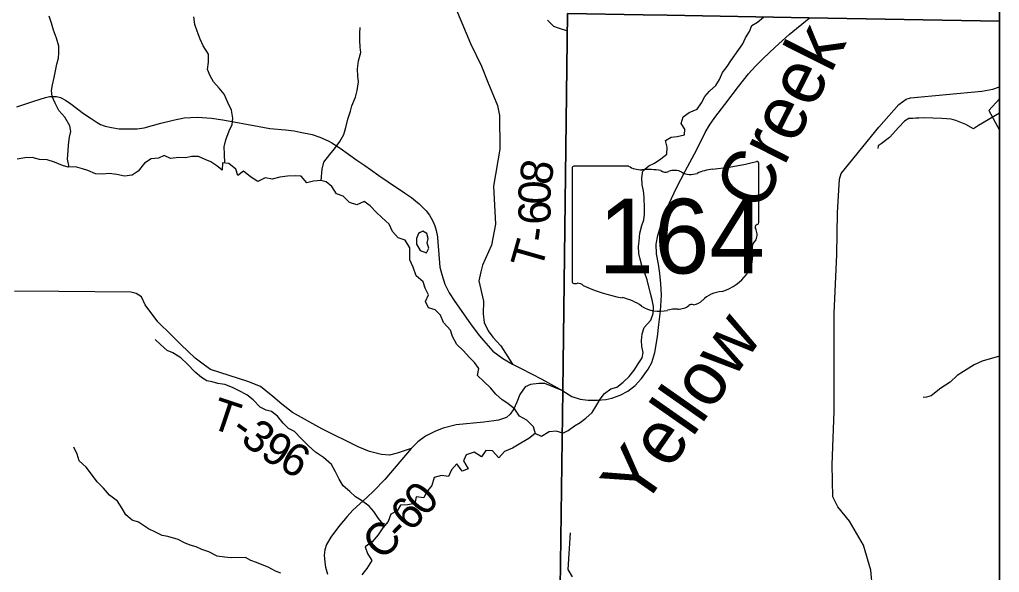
# Model space of a CAD drawing. Extents: x -3.6 to 34, y 0 to 32.8.
# Drawn here: x 1.441 to 3.17, y 27.961 to 28.937 of the extents above; entities that cross this region are included whole.
import ezdxf

# ---------------------------------------------------------------- set-up
doc = ezdxf.new("R2010")
doc.units = 0
for name, color, linetype in [('GM_X_Corporation', 7, 'Continuous'), ('GM_X_County_Road', 7, 'Continuous'), ('GM_X_County_Road_Text', 7, 'Continuous'), ('GM_X_Minor_Lake', 7, 'Continuous'), ('GM_X_Minor_River', 7, 'Continuous'), ('GM_X_Minor_River_Text', 7, 'Continuous'), ('GM_X_State_Location', 7, 'Continuous'), ('GM_X_State_Route', 7, 'Continuous'), ('GM_X_State_Shield', 7, 'Continuous'), ('GM_X_Township_Road', 7, 'Continuous'), ('GM_X_Township_Road_Text', 7, 'Continuous'), ('SH_Data', 7, 'Continuous')]:
    doc.layers.add(name, color=color, linetype=linetype)

msp = doc.modelspace()

# ---------------------------------------------------------------- linework, layer by layer
at = {"layer": 'GM_X_Corporation'}
for points in [[(3.1705, 28.9337), (3.1705, 32.8429), (-3.6295, 32.8429), (-3.6295, 26.0429), (2.3706, 26.0429), (2.3712, 26.0804), (2.3716, 26.1248), (2.3732, 26.2253), (2.3789, 26.6097), (2.3911, 27.5117), (2.3952, 27.9336), (2.3997, 28.282), (2.4082, 28.9473), (2.5416, 28.945), (2.5837, 28.9442), (2.8343, 28.9397)], [(2.3706, 26.0429), (3.1705, 26.0429), (3.1705, 28.9337), (2.8343, 28.9397), (2.5837, 28.9442), (2.5416, 28.945), (2.4082, 28.9473), (2.3997, 28.282), (2.3952, 27.9336), (2.3911, 27.5117), (2.3789, 26.6097), (2.3732, 26.2253), (2.3716, 26.1248), (2.3712, 26.0804)], [(2.3706, 26.0429), (3.1705, 26.0429), (3.1705, 28.9337), (2.8343, 28.9397), (2.5837, 28.9442), (2.5416, 28.945), (2.4082, 28.9473), (2.3997, 28.282), (2.3952, 27.9336), (2.3911, 27.5117), (2.3789, 26.6097), (2.3732, 26.2253), (2.3716, 26.1248), (2.3712, 26.0804)], [(3.1705, 28.7416), (3.1705, 28.7968), (3.1518, 28.7764)]]:
    msp.add_lwpolyline(points, close=True, dxfattribs=at)
msp.add_lwpolyline([(-2.8635, 26.0429), (2.3706, 26.0429), (2.3712, 26.0804), (2.3716, 26.1248), (2.3732, 26.2253), (2.3789, 26.6097), (2.3911, 27.5117), (2.3952, 27.9336), (2.3997, 28.282), (2.4082, 28.9473), (2.5416, 28.945), (2.5837, 28.9442), (2.8343, 28.9397), (3.1705, 28.9337), (3.1705, 30.458), (3.0419, 30.4594), (1.7819, 30.4857), (1.2437, 30.4948), (0.4055, 30.5105), (0.3556, 30.5115), (0.2578, 30.5133), (0.2583, 30.5905), (-0.398, 30.5946), (-0.453, 30.5952)], dxfattribs=at)
at = {"layer": 'GM_X_County_Road'}
for points in [[(2.9463, 27.9329), (2.9438, 27.9647), (2.9304, 28.0089), (2.9061, 28.0513), (2.8855, 28.0764), (2.8764, 28.094), (2.8753, 28.1506), (2.8787, 28.2452), (2.879, 28.4183), (2.8834, 28.5213), (2.8846, 28.5957), (2.8868, 28.6353), (2.8883, 28.655), (2.8911, 28.665), (2.9577, 28.7468), (2.9932, 28.7866), (3.0059, 28.7963), (3.0138, 28.7987), (3.1397, 28.8103), (3.159, 28.8137), (3.1705, 28.8181)], [(2.3999, 28.2815), (2.3681, 28.294), (2.3573, 28.2942), (2.343, 28.2927), (2.3333, 28.2884), (2.3237, 28.2746), (2.3187, 28.2615), (2.3134, 28.2497), (2.3066, 28.2402), (2.3001, 28.2345), (2.2931, 28.2316), (2.2862, 28.2297), (2.278, 28.2281), (2.2604, 28.2261), (2.2115, 28.2213), (2.1887, 28.2155), (2.1753, 28.21), (2.1575, 28.2011), (2.1438, 28.1912), (2.1319, 28.1798), (2.0855, 28.1247), (2.0661, 28.1046), (2.054, 28.093), (2.0293, 28.0706), (2.0189, 28.0593), (2.0061, 28.0443), (1.9966, 28.0316), (1.9902, 28.023), (1.9825, 28.0099), (1.9797, 28.0006), (1.9783, 27.9913), (1.9795, 27.9791), (1.9809, 27.9702), (1.9841, 27.9578)]]:
    msp.add_lwpolyline(points, dxfattribs=at)
at = {"layer": 'GM_X_Minor_Lake'}
for points in [[(2.1482, 28.5609), (2.1449, 28.5592), (2.1416, 28.5505), (2.1414, 28.5402), (2.1481, 28.5289), (2.1594, 28.5249)], [(2.1594, 28.5249), (2.1634, 28.5329), (2.1606, 28.542), (2.162, 28.5504), (2.16, 28.5591), (2.1528, 28.5631), (2.1482, 28.5609)]]:
    msp.add_lwpolyline(points, dxfattribs=at)
at = {"layer": 'GM_X_Minor_River'}
for points in [[(1.5283, 28.6764), (1.5257, 28.6903), (1.5266, 28.7055), (1.5269, 28.7154), (1.5289, 28.7291), (1.5314, 28.7393), (1.5294, 28.7492), (1.5208, 28.7642), (1.5104, 28.7762), (1.5038, 28.789), (1.4983, 28.8011), (1.4974, 28.8113), (1.4988, 28.8215), (1.5016, 28.8345), (1.5041, 28.8463), (1.5065, 28.8581), (1.5098, 28.8684), (1.51, 28.8782), (1.5102, 28.89), (1.5058, 28.904), (1.5007, 28.9179), (1.4971, 28.9304), (1.4931, 28.9425)], [(1.8033, 28.6834), (1.8026, 28.699), (1.802, 28.7119), (1.8048, 28.7245), (1.8107, 28.7401), (1.8162, 28.7516), (1.8171, 28.7626), (1.815, 28.777), (1.8084, 28.7905), (1.8017, 28.8049), (1.7932, 28.8157), (1.7829, 28.827), (1.777, 28.8375), (1.7723, 28.8488), (1.7744, 28.8614), (1.7742, 28.8754), (1.7649, 28.8904), (1.7594, 28.9021), (1.7546, 28.9161), (1.7503, 28.9281), (1.7482, 28.9418)], [(2.3998, 28.2064), (2.4095, 28.2114), (2.4204, 28.2193), (2.4305, 28.2257), (2.4402, 28.2328), (2.4514, 28.243), (2.4583, 28.2539), (2.4655, 28.2666), (2.4732, 28.2767), (2.4844, 28.2847), (2.495, 28.2876), (2.5066, 28.2964), (2.5169, 28.3069), (2.5258, 28.3175), (2.5327, 28.3287), (2.54, 28.3396), (2.5416, 28.3491), (2.5394, 28.3597), (2.5387, 28.3703), (2.5399, 28.3818), (2.5434, 28.3933), (2.5549, 28.4058), (2.5595, 28.4181), (2.5599, 28.4299), (2.5576, 28.442), (2.5543, 28.4533), (2.5486, 28.4775), (2.5437, 28.4907), (2.54, 28.5005), (2.5361, 28.514), (2.5339, 28.5239), (2.5336, 28.536), (2.5345, 28.5456), (2.536, 28.5597), (2.5394, 28.5731), (2.5429, 28.5831), (2.5438, 28.593), (2.5439, 28.6033), (2.5433, 28.623), (2.5422, 28.6344), (2.5396, 28.645), (2.5393, 28.6575), (2.5412, 28.6698), (2.5516, 28.6784), (2.5614, 28.6833), (2.573, 28.6908), (2.5834, 28.6991), (2.5842, 28.7113), (2.5812, 28.723), (2.5913, 28.7294), (2.6015, 28.7301), (2.6144, 28.7331), (2.6153, 28.743), (2.6089, 28.7531), (2.6123, 28.765), (2.6228, 28.7726), (2.6367, 28.7783), (2.6444, 28.7899), (2.6505, 28.8007), (2.659, 28.8105), (2.6698, 28.8203), (2.6763, 28.8312), (2.6817, 28.8431), (2.6901, 28.854), (2.6963, 28.8637), (2.7033, 28.8738), (2.7106, 28.8839), (2.7176, 28.894), (2.7222, 28.9044), (2.7291, 28.9156), (2.7334, 28.926), (2.7436, 28.9322), (2.7539, 28.9409)], [(1.9731, 28.6525), (1.9751, 28.6724), (1.978, 28.685), (1.9887, 28.6988), (1.9965, 28.7084), (2.0062, 28.7214), (2.0132, 28.7337), (2.0168, 28.7459), (2.0203, 28.7607), (2.0251, 28.7748), (2.0275, 28.7847), (2.0338, 28.7996), (2.0366, 28.8114), (2.039, 28.827), (2.0381, 28.8365), (2.0375, 28.8497), (2.0392, 28.8638), (2.0432, 28.8783), (2.0423, 28.8881), (2.0417, 28.9003), (2.0415, 28.9128), (2.0421, 28.9227)], [(2.4089, 28.916), (2.3937, 28.9211), (2.3838, 28.9247), (2.3726, 28.9356)], [(3.1705, 28.7715), (3.1336, 28.7496), (3.1246, 28.7441), (3.1112, 28.7514), (3.0936, 28.7586), (3.0855, 28.7611), (3.0688, 28.7619), (3.0369, 28.7631), (3.0285, 28.7629), (3.0228, 28.7624), (3.0179, 28.7619), (3.0107, 28.7618), (3.0028, 28.7574), (2.9931, 28.7466), (2.9764, 28.7288), (2.9618, 28.7171), (2.9566, 28.7139), (2.9559, 28.709)], [(2.3513, 28.2054), (2.3479, 28.2178), (2.3364, 28.2293), (2.3234, 28.2367), (2.3149, 28.2491), (2.3026, 28.2592), (2.2927, 28.2655), (2.2816, 28.2752), (2.2723, 28.2868), (2.2601, 28.2976), (2.2489, 28.3081), (2.2514, 28.321), (2.244, 28.3312), (2.2344, 28.3405), (2.2244, 28.3517), (2.2125, 28.3633), (2.2051, 28.3773), (2.2016, 28.3886), (2.1892, 28.4021), (2.1838, 28.4149), (2.1742, 28.4242), (2.1624, 28.4278), (2.1573, 28.4391), (2.1628, 28.451), (2.1569, 28.4627), (2.1533, 28.474), (2.1411, 28.4844), (2.1356, 28.4995), (2.1297, 28.5123), (2.1299, 28.5245), (2.1297, 28.534), (2.1216, 28.5471), (2.1094, 28.5515), (2.0994, 28.5627), (2.0935, 28.5755), (2.0805, 28.5875), (2.0701, 28.5968), (2.0598, 28.6077), (2.049, 28.6155), (2.0363, 28.6096), (2.023, 28.6136), (2.0122, 28.6248), (2.0004, 28.6292), (1.9923, 28.6423), (1.9819, 28.6501), (1.9724, 28.6526), (1.9596, 28.6517), (1.9479, 28.6485), (1.9379, 28.6605), (1.928, 28.6611), (1.914, 28.6605), (1.9004, 28.6584), (1.8865, 28.6548), (1.8743, 28.6572), (1.8612, 28.651), (1.8486, 28.6591), (1.836, 28.6688), (1.8262, 28.6614), (1.8223, 28.6724), (1.81, 28.6828), (1.799, 28.6838), (1.7985, 28.6709), (1.7889, 28.6787), (1.7786, 28.6854), (1.7683, 28.6898), (1.7565, 28.6949), (1.7444, 28.6947), (1.7342, 28.6927), (1.7217, 28.6933), (1.7073, 28.6915), (1.6963, 28.6967), (1.6858, 28.692), (1.6733, 28.691), (1.6613, 28.6833), (1.6502, 28.669), (1.6397, 28.6621), (1.6261, 28.6603), (1.6128, 28.6632), (1.5988, 28.6649), (1.5874, 28.6635), (1.5746, 28.6645), (1.5616, 28.67), (1.5521, 28.6733), (1.5396, 28.6769), (1.5267, 28.6763), (1.5164, 28.6792), (1.5027, 28.6847), (1.4898, 28.689), (1.4758, 28.6899), (1.4629, 28.6932), (1.4504, 28.6926), (1.4368, 28.6905)], [(2.0851, 28.0432), (2.0745, 28.0562), (2.066, 28.0682), (2.0579, 28.0779), (2.0445, 28.0876), (2.0338, 28.0943), (2.0239, 28.1036), (2.0123, 28.1137), (2.005, 28.1253), (1.9987, 28.1382), (1.9913, 28.1513), (1.9775, 28.1636), (1.9634, 28.1733), (1.9507, 28.1845), (1.9377, 28.1972), (1.9261, 28.2095), (1.9158, 28.2151), (1.9063, 28.224), (1.8962, 28.2368), (1.8855, 28.2446), (1.876, 28.2471), (1.8657, 28.2527), (1.8534, 28.2654), (1.8419, 28.2743), (1.8282, 28.2813), (1.8164, 28.2872), (1.8031, 28.2927), (1.7909, 28.2944), (1.781, 28.2973), (1.7716, 28.2987), (1.762, 28.305), (1.7509, 28.3143), (1.7367, 28.3289), (1.7252, 28.3393), (1.7114, 28.3486), (1.7011, 28.3526), (1.6896, 28.3631), (1.68, 28.3717)], [(3.1705, 28.3426), (3.1403, 28.3335), (3.126, 28.3271), (3.1072, 28.3157), (3.0959, 28.3082), (3.0833, 28.2966), (3.0668, 28.2859), (3.0499, 28.2727), (3.0416, 28.2702), (3.0356, 28.2697)], [(2.3998, 28.2064), (2.3878, 28.2104), (2.3757, 28.2091), (2.3622, 28.2005), (2.3508, 28.2057), (2.3399, 28.1971), (2.3257, 28.189), (2.311, 28.18), (2.2971, 28.1745), (2.2867, 28.163), (2.2759, 28.1753), (2.2638, 28.1759), (2.2564, 28.1648), (2.2434, 28.1729), (2.2291, 28.1685), (2.2243, 28.1575), (2.2325, 28.1439), (2.2223, 28.1396), (2.2127, 28.1524), (2.2034, 28.142), (2.1979, 28.1301), (2.1858, 28.1318), (2.1726, 28.1282), (2.1686, 28.1141), (2.159, 28.1022), (2.1542, 28.0927), (2.1409, 28.094), (2.1388, 28.0826), (2.126, 28.0801), (2.1135, 28.0795), (2.1076, 28.0692), (2.096, 28.0637), (2.0916, 28.0508), (2.082, 28.0396), (2.0738, 28.0273), (2.0634, 28.015), (2.0507, 28.0061), (2.055, 27.994), (2.0624, 27.9816), (2.0539, 27.9675), (2.045, 27.9567)], [(1.9019, 27.9595), (1.8924, 27.9631), (1.8794, 27.9698), (1.8688, 27.9742), (1.8589, 27.9782), (1.849, 27.9818), (1.8394, 27.987), (1.8145, 27.9866), (1.8024, 27.9876), (1.7895, 27.9893), (1.775, 27.9971), (1.7628, 28.0014), (1.7525, 28.0058), (1.7419, 28.0091), (1.732, 28.0127), (1.7205, 28.019), (1.7027, 28.0241), (1.6924, 28.0262), (1.6806, 28.0321), (1.6684, 28.0376), (1.6505, 28.0495), (1.6394, 28.0531), (1.6283, 28.0624), (1.6221, 28.0733), (1.6136, 28.0865), (1.5998, 28.0973), (1.589, 28.1096), (1.5779, 28.1205), (1.5678, 28.1344), (1.5582, 28.1464), (1.5463, 28.1579), (1.5423, 28.1693), (1.5368, 28.1821)], [(2.413, 28.0305), (2.4088, 27.9659), (2.4163, 27.9528)]]:
    msp.add_lwpolyline(points, dxfattribs=at)
at = {"layer": 'GM_X_State_Route'}
for points in [[(2.5694, 28.3986), (2.5723, 28.4222), (2.5741, 28.4499), (2.5727, 28.4704), (2.5709, 28.4882), (2.5684, 28.5049), (2.5651, 28.5234), (2.5645, 28.5401), (2.5677, 28.5557), (2.576, 28.5824), (2.5877, 28.6122), (2.6006, 28.6397), (2.6157, 28.6692), (2.6323, 28.6994), (2.6419, 28.7181), (2.6511, 28.7376), (2.6589, 28.7502), (2.6682, 28.7637), (2.6857, 28.7867), (2.7099, 28.8185), (2.7274, 28.8408), (2.7401, 28.8542), (2.7532, 28.8681), (2.7745, 28.8877), (2.7996, 28.9101), (2.8345, 28.9391)], [(1.436, 28.7827), (1.4658, 28.7929), (1.4865, 28.7991), (1.4937, 28.8007), (1.5008, 28.8009), (1.506, 28.8007), (1.5128, 28.7989), (1.5217, 28.7945), (1.5312, 28.7879), (1.5538, 28.7709), (1.5653, 28.763), (1.5776, 28.755), (1.5836, 28.7515), (1.592, 28.7486), (1.6029, 28.7459), (1.6166, 28.7439), (1.6321, 28.7436), (1.6483, 28.7439), (1.661, 28.7454), (1.69, 28.7537), (1.7121, 28.7594), (1.7316, 28.763), (1.7549, 28.7643), (1.7794, 28.7626), (1.7994, 28.76), (1.8636, 28.7477), (1.8827, 28.7447), (1.9102, 28.7421), (1.9255, 28.74), (1.9364, 28.738), (1.9572, 28.7337), (1.971, 28.7293), (1.9857, 28.7224), (1.9921, 28.7191), (2.0065, 28.7099), (2.0363, 28.6888), (2.0505, 28.6788), (2.0601, 28.6719), (2.0748, 28.6615), (2.0915, 28.6502), (2.1203, 28.6307), (2.1324, 28.6224), (2.1396, 28.6166), (2.1463, 28.6114), (2.1549, 28.6027), (2.1583, 28.5989), (2.1642, 28.5915), (2.1675, 28.5862), (2.1708, 28.5798), (2.174, 28.5727), (2.1763, 28.5644), (2.1786, 28.5529), (2.1791, 28.543), (2.1804, 28.5298), (2.1826, 28.4994), (2.186, 28.4864), (2.1914, 28.4696), (2.1991, 28.4546), (2.2093, 28.439), (2.2202, 28.4229), (2.238, 28.398), (2.2529, 28.3783), (2.2598, 28.3699), (2.2764, 28.3515), (2.2941, 28.3386), (2.3111, 28.3286), (2.3265, 28.3209), (2.3625, 28.3017), (2.3999, 28.2815)], [(2.3999, 28.2815), (2.4159, 28.2715), (2.4304, 28.2668), (2.4445, 28.2647), (2.4611, 28.2646), (2.4759, 28.2663), (2.4865, 28.2684), (2.5008, 28.2735), (2.5144, 28.2809), (2.5275, 28.2909), (2.5387, 28.3033), (2.5506, 28.3197), (2.5569, 28.3312), (2.562, 28.3491), (2.5669, 28.3769), (2.5694, 28.3986)]]:
    msp.add_lwpolyline(points, dxfattribs=at)
at = {"layer": 'GM_X_State_Shield'}
for p, q in [((2.5158, 28.6779), (2.4193, 28.6779)), ((2.7456, 28.5782), (2.7456, 28.6829)), ((2.4161, 28.6745), (2.4161, 28.4744)), ((2.7456, 28.5782), (2.7456, 28.5782))]:
    msp.add_line(p, q, dxfattribs=at)
for centre, major_axis, start_param, end_param in [((2.4198, 28.6749), (0.00382, 0), 1.712693, 3.28349), ((2.5388, 28.7012), (0.037, 0), 4.042523, 4.731795), ((2.6282, 28.9508), (0.3495, 0), 4.814394, 5.042369), ((2.742, 28.6833), (0.00367, 0), 6.141152, 7.989035), ((2.5511, 28.5656), (0.133, 0), 1.404758, 1.657858), ((2.5813, 28.676), (0.0107, 0), 3.836095, 5.185415), ((2.597, 28.6528), (0.0222, 0), 0.950623, 2.079405), ((2.6256, 28.6846), (0.0267, 0), 4.081561, 5.145723), ((2.6728, 28.6168), (0.0703, 0), 1.699011, 2.107814), ((2.7448, 28.5705), (0.00568, 0), 1.883978, 3.671073), ((2.7417, 28.5778), (0.00393, 0), 5.05454, 6.418171), ((2.7087, 28.5573), (0.0341, 0), 5.934695, 6.695948), ((2.7588, 28.5344), (0.0248, 0), 2.387724, 3.262537), ((2.6478, 28.5211), (0.0874, 0), 5.101752, 6.440018), ((2.4199, 28.4739), (0.00385, 0), 3.00124, 4.508301), ((2.4204, 28.4944), (0.0294, 0), 4.665946, 4.897461), ((2.4265, 28.4628), (0.0106, 0), 0.519207, 1.627899), ((2.5603, 28.6426), (0.2524, 0), 4.195997, 4.488961), ((2.6847, 28.4182), (0.0479, 0), 1.647645, 2.488434), ((2.485, 28.3845), (0.079, 0), 0.823519, 1.323587), ((2.624, 28.455), (0.0282, 0), 4.937069, 5.64225), ((2.5705, 28.4618), (0.0501, 0), 4.026481, 4.996735), ((2.5994, 28.3927), (0.0412, 0), 1.495662, 1.94098), ((2.6031, 28.4469), (0.0267, 0), 4.691044, 5.507374), ((2.6272, 28.4275), (0.00752, 0), 1.147584, 2.315152)]:
    msp.add_ellipse(centre, major_axis=major_axis, ratio=0.8, start_param=start_param, end_param=end_param, dxfattribs=at)
at = {"layer": 'GM_X_Township_Road'}
for points in [[(2.2112, 28.9561), (2.2367, 28.8943), (2.2565, 28.8547), (2.2672, 28.8262), (2.2846, 28.7852), (2.2881, 28.7671), (2.2888, 28.7081), (2.2774, 28.6424), (2.2812, 28.5756), (2.2741, 28.5386), (2.2578, 28.5029), (2.2549, 28.4915), (2.2513, 28.4756), (2.2597, 28.4398), (2.2593, 28.4174), (2.261, 28.4022), (2.2681, 28.3872), (2.2764, 28.376), (2.2905, 28.3608), (2.3111, 28.3286)], [(2.1319, 28.1798), (2.1074, 28.171), (2.0939, 28.1679), (2.0798, 28.1687), (2.0585, 28.1743), (2.0387, 28.1822), (1.9743, 28.2145), (1.9225, 28.243), (1.9037, 28.2577), (1.888, 28.2716), (1.8662, 28.2892), (1.8437, 28.2978), (1.7777, 28.3189), (1.7649, 28.3282), (1.7505, 28.339), (1.7256, 28.363), (1.7089, 28.3798), (1.6848, 28.403), (1.6624, 28.433), (1.6559, 28.4472), (1.6468, 28.4531), (1.6373, 28.4555), (1.5099, 28.4565), (1.4317, 28.4572)]]:
    msp.add_lwpolyline(points, dxfattribs=at)
at = {"layer": 'SH_Data'}
msp.add_line((3.1705, 32.8429), (3.1705, 26.0429), dxfattribs=at)

# ---------------------------------------------------------------- texts
at = {"layer": 'GM_X_County_Road_Text'}
for s, rotation, p in [('0', 48.1199, (2.1565, 28.0573)), ('6', 46.2013, (2.1309, 28.0305)), ('C', 45.0345, (2.0806, 27.98)), ('-', 45.3225, (2.1138, 28.0132))]:
    msp.add_text(s, height=0.0568, rotation=rotation, dxfattribs=at).set_placement(p)
at = {"layer": 'GM_X_Minor_River_Text'}
for s, height, rotation, p in [('Creek', 0.09469, 63.2958, (2.7495, 28.5948)), ('Yellow', 0.09471, 54.983, (2.5393, 28.0706))]:
    msp.add_text(s, height=height, rotation=rotation, dxfattribs=at).set_placement(p)
at = {"layer": 'GM_X_State_Location'}
for s in ['s', 'r']:
    msp.add_text(s, height=0.000189, dxfattribs=at).set_placement((2.5771, 28.5611))
msp.add_text('164', height=0.000189, rotation=0, dxfattribs=at).set_placement((2.5103, 28.5474))
at = {"layer": 'GM_X_State_Shield'}
msp.add_text('164', height=0.13184, dxfattribs=at).set_placement((2.4626, 28.4885))
at = {"layer": 'GM_X_Township_Road_Text'}
for s, rotation, p in [('8', 80.8384, (2.3785, 28.6427)), ('0', 88.5635, (2.3778, 28.6097)), ('6', 91.7241, (2.3789, 28.5756)), ('-', 82.1938, (2.3751, 28.5422)), ('T', 73.9781, (2.3616, 28.4927)), ('T', 341.4146, (1.7743, 28.2169)), ('3', 320.423, (1.8288, 28.1925)), ('-', 324.4337, (1.8106, 28.2054)), ('9', 328.8432, (1.8632, 28.1649)), ('6', 331.7368, (1.8958, 28.1452))]:
    msp.add_text(s, height=0.0568, rotation=rotation, dxfattribs=at).set_placement(p)

doc.saveas('drawing.dxf')
